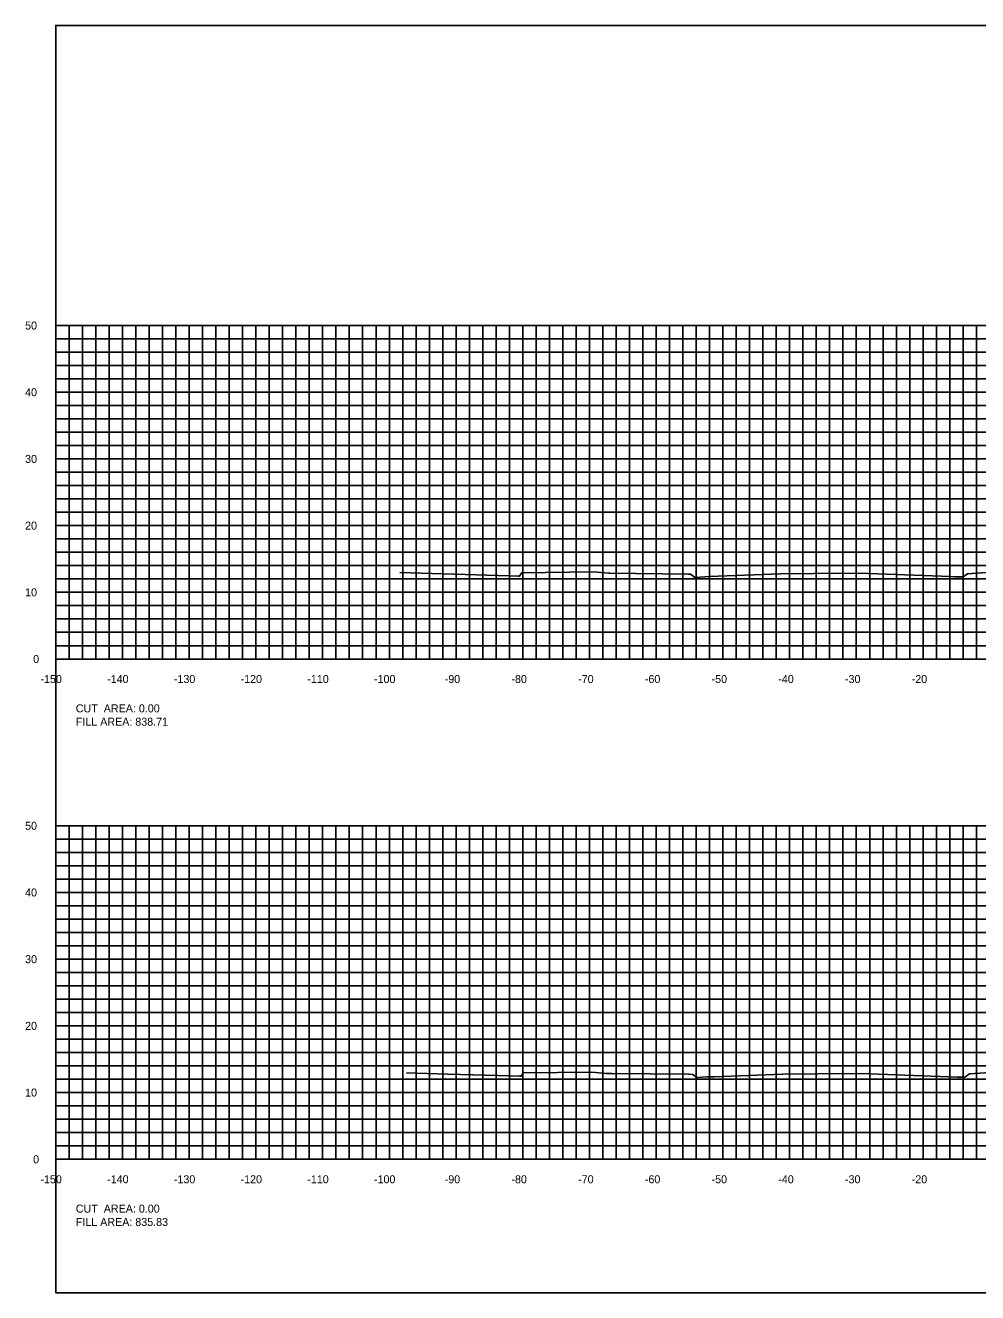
# Model space of a CAD drawing. Extents: x 1797714 to 1804825, y 249015 to 250269.
# Drawn here: x 1803836.4 to 1803979.2, y 250079.4 to 250269.4 of the extents above; entities that cross this region are included whole.
import ezdxf

# ---------------------------------------------------------------- set-up
doc = ezdxf.new("R2010")
doc.units = 0
for name, color, linetype in [('10', 7, 'Continuous'), ('31', 7, 'Continuous'), ('60', 7, 'Continuous'), ('ANNO-TXT', 7, 'Continuous'), ('Level 62', 7, 'Continuous'), ('M-ROADS', 7, 'Continuous')]:
    doc.layers.add(name, color=color, linetype=linetype)

msp = doc.modelspace()

# ---------------------------------------------------------------- linework, layer by layer
msp.add_lwpolyline([(1803841, 250079.43), (1804141, 250079.43), (1804141, 250269.43), (1803841, 250269.43)], close=True)
at = {"layer": '60'}
for p, q in [((1803840.94, 250224.43), (1803841, 250224.43)), ((1803841, 250174.43), (1803841, 250224.43)), ((1803840.94, 250214.43), (1803841, 250214.43)), ((1803840.94, 250204.43), (1803841, 250204.43)), ((1803840.94, 250194.43), (1803841, 250194.43)), ((1803840.94, 250184.43), (1803841, 250184.43)), ((1803840.94, 250174.43), (1803841, 250174.43)), ((1803841, 250174.43), (1804141, 250174.43)), ((1803841, 250174.37), (1803841, 250174.43)), ((1803851, 250174.37), (1803851, 250174.43)), ((1803861, 250174.37), (1803861, 250174.43)), ((1803871, 250174.37), (1803871, 250174.43)), ((1803881, 250174.37), (1803881, 250174.43)), ((1803891, 250174.37), (1803891, 250174.43)), ((1803901, 250174.37), (1803901, 250174.43)), ((1803911, 250174.37), (1803911, 250174.43)), ((1803921, 250174.37), (1803921, 250174.43)), ((1803931, 250174.37), (1803931, 250174.43)), ((1803941, 250174.37), (1803941, 250174.43)), ((1803951, 250174.37), (1803951, 250174.43)), ((1803961, 250174.37), (1803961, 250174.43)), ((1803971, 250174.37), (1803971, 250174.43)), ((1803840.94, 250149.43), (1803841, 250149.43)), ((1803841, 250099.43), (1803841, 250149.43)), ((1803840.94, 250139.43), (1803841, 250139.43)), ((1803840.94, 250129.43), (1803841, 250129.43)), ((1803840.94, 250119.43), (1803841, 250119.43)), ((1803840.94, 250109.43), (1803841, 250109.43)), ((1803840.94, 250099.43), (1803841, 250099.43)), ((1803841, 250099.43), (1804141, 250099.43)), ((1803841, 250099.37), (1803841, 250099.43)), ((1803851, 250099.37), (1803851, 250099.43)), ((1803861, 250099.37), (1803861, 250099.43)), ((1803871, 250099.37), (1803871, 250099.43)), ((1803881, 250099.37), (1803881, 250099.43)), ((1803891, 250099.37), (1803891, 250099.43)), ((1803901, 250099.37), (1803901, 250099.43)), ((1803911, 250099.37), (1803911, 250099.43)), ((1803921, 250099.37), (1803921, 250099.43)), ((1803931, 250099.37), (1803931, 250099.43)), ((1803941, 250099.37), (1803941, 250099.43)), ((1803951, 250099.37), (1803951, 250099.43)), ((1803961, 250099.37), (1803961, 250099.43)), ((1803971, 250099.37), (1803971, 250099.43))]:
    msp.add_line(p, q, dxfattribs=at)
at = {"layer": 'Level 62'}
for p, q in [((1803841, 250224.43), (1804141, 250224.43)), ((1803841, 250174.43), (1803841, 250224.43)), ((1803843, 250174.43), (1803843, 250224.43)), ((1803845, 250174.43), (1803845, 250224.43)), ((1803847, 250174.43), (1803847, 250224.43)), ((1803849, 250174.43), (1803849, 250224.43)), ((1803851, 250174.43), (1803851, 250224.43)), ((1803853, 250174.43), (1803853, 250224.43)), ((1803855, 250174.43), (1803855, 250224.43)), ((1803857, 250174.43), (1803857, 250224.43)), ((1803859, 250174.43), (1803859, 250224.43)), ((1803861, 250174.43), (1803861, 250224.43)), ((1803863, 250174.43), (1803863, 250224.43)), ((1803865, 250174.43), (1803865, 250224.43)), ((1803867, 250174.43), (1803867, 250224.43)), ((1803869, 250174.43), (1803869, 250224.43)), ((1803871, 250174.43), (1803871, 250224.43)), ((1803873, 250174.43), (1803873, 250224.43)), ((1803875, 250174.43), (1803875, 250224.43)), ((1803877, 250174.43), (1803877, 250224.43)), ((1803879, 250174.43), (1803879, 250224.43)), ((1803881, 250174.43), (1803881, 250224.43)), ((1803883, 250174.43), (1803883, 250224.43)), ((1803885, 250174.43), (1803885, 250224.43)), ((1803887, 250174.43), (1803887, 250224.43)), ((1803889, 250174.43), (1803889, 250224.43)), ((1803891, 250174.43), (1803891, 250224.43)), ((1803893, 250174.43), (1803893, 250224.43)), ((1803895, 250174.43), (1803895, 250224.43)), ((1803897, 250174.43), (1803897, 250224.43)), ((1803899, 250174.43), (1803899, 250224.43)), ((1803901, 250174.43), (1803901, 250224.43)), ((1803903, 250174.43), (1803903, 250224.43)), ((1803905, 250174.43), (1803905, 250224.43)), ((1803907, 250174.43), (1803907, 250224.43)), ((1803909, 250174.43), (1803909, 250224.43)), ((1803911, 250174.43), (1803911, 250224.43)), ((1803913, 250174.43), (1803913, 250224.43)), ((1803915, 250174.43), (1803915, 250224.43)), ((1803917, 250174.43), (1803917, 250224.43)), ((1803919, 250174.43), (1803919, 250224.43)), ((1803921, 250174.43), (1803921, 250224.43)), ((1803923, 250174.43), (1803923, 250224.43)), ((1803925, 250174.43), (1803925, 250224.43)), ((1803927, 250174.43), (1803927, 250224.43)), ((1803929, 250174.43), (1803929, 250224.43)), ((1803931, 250174.43), (1803931, 250224.43)), ((1803933, 250174.43), (1803933, 250224.43)), ((1803935, 250174.43), (1803935, 250224.43)), ((1803937, 250174.43), (1803937, 250224.43)), ((1803939, 250174.43), (1803939, 250224.43)), ((1803941, 250174.43), (1803941, 250224.43)), ((1803943, 250174.43), (1803943, 250224.43)), ((1803945, 250174.43), (1803945, 250224.43)), ((1803947, 250174.43), (1803947, 250224.43)), ((1803949, 250174.43), (1803949, 250224.43)), ((1803951, 250174.43), (1803951, 250224.43)), ((1803953, 250174.43), (1803953, 250224.43)), ((1803955, 250174.43), (1803955, 250224.43)), ((1803957, 250174.43), (1803957, 250224.43)), ((1803959, 250174.43), (1803959, 250224.43)), ((1803961, 250174.43), (1803961, 250224.43)), ((1803963, 250174.43), (1803963, 250224.43)), ((1803965, 250174.43), (1803965, 250224.43)), ((1803967, 250174.43), (1803967, 250224.43)), ((1803969, 250174.43), (1803969, 250224.43)), ((1803971, 250174.43), (1803971, 250224.43)), ((1803973, 250174.43), (1803973, 250224.43)), ((1803975, 250174.43), (1803975, 250224.43)), ((1803977, 250174.43), (1803977, 250224.43)), ((1803979, 250174.43), (1803979, 250224.43)), ((1803841, 250222.43), (1804141, 250222.43)), ((1803841, 250220.43), (1804141, 250220.43)), ((1803841, 250218.43), (1804141, 250218.43)), ((1803841, 250216.43), (1804141, 250216.43)), ((1803841, 250214.43), (1804141, 250214.43)), ((1803841, 250212.43), (1804141, 250212.43)), ((1803841, 250210.43), (1804141, 250210.43)), ((1803841, 250208.43), (1804141, 250208.43)), ((1803841, 250206.43), (1804141, 250206.43)), ((1803841, 250204.43), (1804141, 250204.43)), ((1803841, 250202.43), (1804141, 250202.43)), ((1803841, 250200.43), (1804141, 250200.43)), ((1803841, 250198.43), (1804141, 250198.43)), ((1803841, 250196.43), (1804141, 250196.43)), ((1803841, 250194.43), (1804141, 250194.43)), ((1803841, 250192.43), (1804141, 250192.43)), ((1803841, 250190.43), (1804141, 250190.43)), ((1803841, 250188.43), (1804141, 250188.43)), ((1803841, 250186.43), (1804141, 250186.43)), ((1803841, 250184.43), (1804141, 250184.43)), ((1803841, 250182.43), (1804141, 250182.43)), ((1803841, 250180.43), (1804141, 250180.43)), ((1803841, 250178.43), (1804141, 250178.43)), ((1803841, 250176.43), (1804141, 250176.43)), ((1803841, 250174.43), (1804141, 250174.43)), ((1803841, 250149.43), (1804141, 250149.43)), ((1803841, 250099.43), (1803841, 250149.43)), ((1803843, 250099.43), (1803843, 250149.43)), ((1803845, 250099.43), (1803845, 250149.43)), ((1803847, 250099.43), (1803847, 250149.43)), ((1803849, 250099.43), (1803849, 250149.43)), ((1803851, 250099.43), (1803851, 250149.43)), ((1803853, 250099.43), (1803853, 250149.43)), ((1803855, 250099.43), (1803855, 250149.43)), ((1803857, 250099.43), (1803857, 250149.43)), ((1803859, 250099.43), (1803859, 250149.43)), ((1803861, 250099.43), (1803861, 250149.43)), ((1803863, 250099.43), (1803863, 250149.43)), ((1803865, 250099.43), (1803865, 250149.43)), ((1803867, 250099.43), (1803867, 250149.43)), ((1803869, 250099.43), (1803869, 250149.43)), ((1803871, 250099.43), (1803871, 250149.43)), ((1803873, 250099.43), (1803873, 250149.43)), ((1803875, 250099.43), (1803875, 250149.43)), ((1803877, 250099.43), (1803877, 250149.43)), ((1803879, 250099.43), (1803879, 250149.43)), ((1803881, 250099.43), (1803881, 250149.43)), ((1803883, 250099.43), (1803883, 250149.43)), ((1803885, 250099.43), (1803885, 250149.43)), ((1803887, 250099.43), (1803887, 250149.43)), ((1803889, 250099.43), (1803889, 250149.43)), ((1803891, 250099.43), (1803891, 250149.43)), ((1803893, 250099.43), (1803893, 250149.43)), ((1803895, 250099.43), (1803895, 250149.43)), ((1803897, 250099.43), (1803897, 250149.43)), ((1803899, 250099.43), (1803899, 250149.43)), ((1803901, 250099.43), (1803901, 250149.43)), ((1803903, 250099.43), (1803903, 250149.43)), ((1803905, 250099.43), (1803905, 250149.43)), ((1803907, 250099.43), (1803907, 250149.43)), ((1803909, 250099.43), (1803909, 250149.43)), ((1803911, 250099.43), (1803911, 250149.43)), ((1803913, 250099.43), (1803913, 250149.43)), ((1803915, 250099.43), (1803915, 250149.43)), ((1803917, 250099.43), (1803917, 250149.43)), ((1803919, 250099.43), (1803919, 250149.43)), ((1803921, 250099.43), (1803921, 250149.43)), ((1803923, 250099.43), (1803923, 250149.43)), ((1803925, 250099.43), (1803925, 250149.43)), ((1803927, 250099.43), (1803927, 250149.43)), ((1803929, 250099.43), (1803929, 250149.43)), ((1803931, 250099.43), (1803931, 250149.43)), ((1803933, 250099.43), (1803933, 250149.43)), ((1803935, 250099.43), (1803935, 250149.43)), ((1803937, 250099.43), (1803937, 250149.43)), ((1803939, 250099.43), (1803939, 250149.43)), ((1803941, 250099.43), (1803941, 250149.43)), ((1803943, 250099.43), (1803943, 250149.43)), ((1803945, 250099.43), (1803945, 250149.43)), ((1803947, 250099.43), (1803947, 250149.43)), ((1803949, 250099.43), (1803949, 250149.43)), ((1803951, 250099.43), (1803951, 250149.43)), ((1803953, 250099.43), (1803953, 250149.43)), ((1803955, 250099.43), (1803955, 250149.43)), ((1803957, 250099.43), (1803957, 250149.43)), ((1803959, 250099.43), (1803959, 250149.43)), ((1803961, 250099.43), (1803961, 250149.43)), ((1803963, 250099.43), (1803963, 250149.43)), ((1803965, 250099.43), (1803965, 250149.43)), ((1803967, 250099.43), (1803967, 250149.43)), ((1803969, 250099.43), (1803969, 250149.43)), ((1803971, 250099.43), (1803971, 250149.43)), ((1803973, 250099.43), (1803973, 250149.43)), ((1803975, 250099.43), (1803975, 250149.43)), ((1803977, 250099.43), (1803977, 250149.43)), ((1803979, 250099.43), (1803979, 250149.43)), ((1803841, 250147.43), (1804141, 250147.43)), ((1803841, 250145.43), (1804141, 250145.43)), ((1803841, 250143.43), (1804141, 250143.43)), ((1803841, 250141.43), (1804141, 250141.43)), ((1803841, 250139.43), (1804141, 250139.43)), ((1803841, 250137.43), (1804141, 250137.43)), ((1803841, 250135.43), (1804141, 250135.43)), ((1803841, 250133.43), (1804141, 250133.43)), ((1803841, 250131.43), (1804141, 250131.43)), ((1803841, 250129.43), (1804141, 250129.43)), ((1803841, 250127.43), (1804141, 250127.43)), ((1803841, 250125.43), (1804141, 250125.43)), ((1803841, 250123.43), (1804141, 250123.43)), ((1803841, 250121.43), (1804141, 250121.43)), ((1803841, 250119.43), (1804141, 250119.43)), ((1803841, 250117.43), (1804141, 250117.43)), ((1803841, 250115.43), (1804141, 250115.43)), ((1803841, 250113.43), (1804141, 250113.43)), ((1803841, 250111.43), (1804141, 250111.43)), ((1803841, 250109.43), (1804141, 250109.43)), ((1803841, 250107.43), (1804141, 250107.43)), ((1803841, 250105.43), (1804141, 250105.43)), ((1803841, 250103.43), (1804141, 250103.43)), ((1803841, 250101.43), (1804141, 250101.43)), ((1803841, 250099.43), (1804141, 250099.43))]:
    msp.add_line(p, q, dxfattribs=at)
at = {"layer": 'M-ROADS'}
for points in [[(1803892.56, 250187.42), (1803899.08, 250187.18), (1803908.89, 250186.92), (1803910.31, 250186.87), (1803910.49, 250186.87), (1803910.54, 250186.94), (1803910.84, 250187.36), (1803921.54, 250187.5), (1803923.83, 250187.3), (1803924.03, 250187.3), (1803935.81, 250187.15), (1803936.16, 250187.14), (1803936.74, 250186.68), (1803936.75, 250186.66), (1803936.81, 250186.66), (1803938.3, 250186.76), (1803938.95, 250186.78), (1803949.64, 250187.21), (1803954.65, 250187.25), (1803961.44, 250187.3), (1803975.11, 250186.78), (1803975.82, 250186.76), (1803975.98, 250186.75), (1803976.07, 250186.75), (1803976.17, 250186.75), (1803976.25, 250186.75), (1803976.31, 250186.75), (1803977.01, 250186.74), (1803977.14, 250186.87), (1803977.68, 250187.22), (1803981.23, 250187.46)], [(1803893.57, 250112.41), (1803899.79, 250112.18), (1803909.17, 250111.93), (1803910.53, 250111.88), (1803910.76, 250111.88), (1803910.82, 250111.97), (1803911.11, 250112.38), (1803921.33, 250112.51), (1803923.52, 250112.31), (1803924.37, 250112.31), (1803935.89, 250112.17), (1803936.51, 250112.15), (1803937.07, 250111.7), (1803937.1, 250111.67), (1803937.18, 250111.67), (1803938.64, 250111.77), (1803939.7, 250111.81), (1803949.96, 250112.21), (1803955.24, 250112.25), (1803961.74, 250112.31), (1803976.11, 250111.76), (1803976.26, 250111.75), (1803976.37, 250111.75), (1803976.48, 250111.75), (1803976.56, 250111.76), (1803976.63, 250111.75), (1803976.68, 250111.76), (1803977.28, 250111.75), (1803977.39, 250111.86), (1803977.96, 250112.23), (1803980.99, 250112.43)]]:
    msp.add_lwpolyline(points, dxfattribs=at)

# ---------------------------------------------------------------- texts
at = {"layer": '10'}
for s, p in [('-150', (1803838.7, 250170.83)), ('-140', (1803848.7, 250170.83)), ('-130', (1803858.7, 250170.83)), ('-120', (1803868.7, 250170.83)), ('-110', (1803878.7, 250170.83)), ('-100', (1803888.7, 250170.83)), ('-90', (1803899.3, 250170.83)), ('-80', (1803909.3, 250170.83)), ('-70', (1803919.3, 250170.83)), ('-60', (1803929.3, 250170.83)), ('-50', (1803939.3, 250170.83)), ('-40', (1803949.3, 250170.83)), ('-30', (1803959.3, 250170.83)), ('-20', (1803969.3, 250170.83)), ('-150', (1803838.7, 250095.83)), ('-140', (1803848.7, 250095.83)), ('-130', (1803858.7, 250095.83)), ('-120', (1803868.7, 250095.83)), ('-110', (1803878.7, 250095.83)), ('-100', (1803888.7, 250095.83)), ('-90', (1803899.3, 250095.83)), ('-80', (1803909.3, 250095.83)), ('-70', (1803919.3, 250095.83)), ('-60', (1803929.3, 250095.83)), ('-50', (1803939.3, 250095.83)), ('-40', (1803949.3, 250095.83)), ('-30', (1803959.3, 250095.83)), ('-20', (1803969.3, 250095.83))]:
    msp.add_text(s, height=1.2, dxfattribs=at).set_placement(p)
at = {"layer": '31'}
for s, p in [('50', (1803836.4, 250223.83)), ('40', (1803836.4, 250213.83)), ('30', (1803836.4, 250203.83)), ('20', (1803836.4, 250193.83)), ('10', (1803836.4, 250183.83)), ('0', (1803837.6, 250173.83)), ('50', (1803836.4, 250148.83)), ('40', (1803836.4, 250138.83)), ('30', (1803836.4, 250128.83)), ('20', (1803836.4, 250118.83)), ('10', (1803836.4, 250108.83)), ('0', (1803837.6, 250098.83))]:
    msp.add_text(s, height=1.2, dxfattribs=at).set_placement(p)
at = {"layer": '60'}
for p in [(1803841, 250174.43), (1803841, 250099.43)]:
    msp.add_text('-', height=0.0001, dxfattribs=at).set_placement(p)
at = {"layer": 'ANNO-TXT'}
for s, p in [('CUT  AREA: 0.00', (1803844, 250166.43)), ('FILL AREA: 838.71', (1803844, 250164.43)), ('CUT  AREA: 0.00', (1803844, 250091.43)), ('FILL AREA: 835.83', (1803844, 250089.43))]:
    msp.add_text(s, height=1.2, dxfattribs=at).set_placement(p)

doc.saveas('drawing.dxf')
